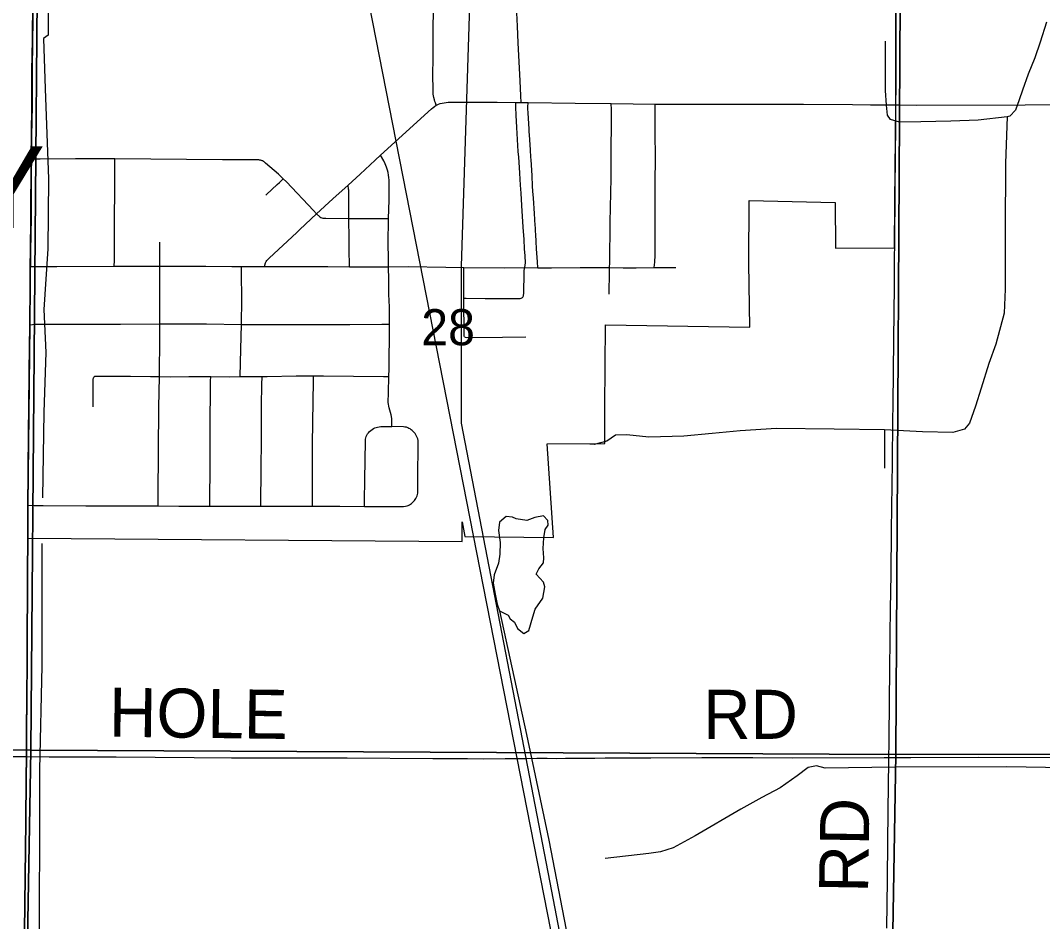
# Model space of a CAD drawing. Extents: x 0 to 34, y 0 to 22.
# Drawn here: x 3.136 to 4.321, y 19.331 to 20.375 of the extents above; entities that cross this region are included whole.
import ezdxf

# ---------------------------------------------------------------- set-up
doc = ezdxf.new("R2010")
doc.units = 0
for name, color, linetype in [('Default', 7, 'Continuous'), ('GM_X_City_Street', 7, 'Continuous'), ('GM_X_Corporation_Text', 7, 'Continuous'), ('GM_X_County_Road', 7, 'Continuous'), ('GM_X_Minor_Lake', 7, 'Continuous'), ('GM_X_Minor_River', 7, 'Continuous'), ('GM_X_Rail_Line', 7, 'Continuous'), ('GM_X_Section', 7, 'Continuous'), ('GM_X_Section_Text', 7, 'Continuous'), ('GM_X_State_Route', 7, 'Continuous'), ('GM_X_Township_Road', 7, 'Continuous'), ('GM_X_Township_Road_Text', 7, 'Continuous')]:
    doc.layers.add(name, color=color, linetype=linetype)

msp = doc.modelspace()

# ---------------------------------------------------------------- linework, layer by layer
at = {"layer": 'Default'}
for points in [[(3.1509, 20.3978), (3.1497, 20.2765), (3.1489, 20.2151), (3.1486, 20.1465), (3.1478, 20.0903), (3.1472, 20.0228), (3.1452, 19.8136), (3.1449, 19.775), (3.6483, 19.7709), (3.6482, 19.7779), (3.6483, 19.7938), (3.6515, 19.7769), (3.7543, 19.7756), (3.747, 19.8843), (3.8135, 19.8846), (3.8135, 19.9261), (3.8144, 20.022), (3.9815, 20.0192), (3.9805, 20.0931), (3.9808, 20.1661), (4.0804, 20.1638), (4.081, 20.1108), (4.1492, 20.1113), (4.1497, 20.1638), (4.1507, 20.2775), (4.1512, 20.5281)], [(3.1509, 20.3978), (3.1503, 20.3518), (3.1498, 20.3169), (3.1497, 20.2765), (3.1493, 20.2417), (3.1489, 20.2181), (3.1489, 20.2151), (3.1489, 20.1988), (3.1486, 20.1602), (3.1486, 20.1465), (3.148, 20.108), (3.1478, 20.0903), (3.1478, 20.0669), (3.1472, 20.0228), (3.1469, 19.9948), (3.1468, 19.9686), (3.1461, 19.9245), (3.1459, 19.8999), (3.1455, 19.8495), (3.1452, 19.8136), (3.145, 19.7885), (3.1449, 19.775), (3.1445, 19.7344), (3.1448, 19.7114), (3.1445, 19.6964), (3.1443, 19.6784), (3.1444, 19.656), (3.1443, 19.6349), (3.1442, 19.6188), (3.144, 19.6032), (3.144, 19.5871), (3.1437, 19.5542), (3.1436, 19.5246), (3.1436, 19.5224), (3.1433, 19.4963), (3.1426, 19.4466), (3.1411, 19.3192)], [(3.1411, 19.3192), (3.1426, 19.4466), (3.1433, 19.4963), (3.1436, 19.5224), (3.1436, 19.5246), (3.1437, 19.5542), (3.144, 19.5871), (3.144, 19.6032), (3.1442, 19.6188), (3.1443, 19.6349), (3.1444, 19.656), (3.1443, 19.6784), (3.1445, 19.6964), (3.1448, 19.7114), (3.1445, 19.7344), (3.1449, 19.775), (3.145, 19.7885), (3.1452, 19.8136), (3.1455, 19.8495), (3.1459, 19.8999), (3.1461, 19.9245), (3.1468, 19.9686), (3.1469, 19.9948), (3.1472, 20.0228), (3.1478, 20.0669), (3.1478, 20.0903), (3.148, 20.108), (3.1486, 20.1465), (3.1486, 20.1602), (3.1489, 20.1988), (3.1489, 20.2151), (3.1489, 20.2181), (3.1493, 20.2417), (3.1497, 20.2765), (3.1498, 20.3169), (3.1503, 20.3518), (3.1509, 20.3978)]]:
    msp.add_lwpolyline(points, dxfattribs=at)
at = {"layer": 'GM_X_City_Street'}
for points in [[(3.6183, 20.2765), (3.6173, 20.2792), (3.6167, 20.2808), (3.6161, 20.2829), (3.6154, 20.2854), (3.6149, 20.2892), (3.6148, 20.293), (3.6145, 20.3135), (3.6147, 20.3294), (3.6149, 20.3686), (3.6166, 20.4417), (3.6174, 20.4802), (3.6179, 20.5203), (3.618, 20.5322)], [(3.7168, 20.2798), (3.7164, 20.2875), (3.7156, 20.3048), (3.7134, 20.3488), (3.7125, 20.368), (3.7108, 20.3996), (3.7102, 20.4101), (3.7092, 20.4275), (3.7088, 20.4343), (3.7083, 20.4442), (3.7067, 20.4746), (3.7063, 20.4832), (3.705, 20.5055), (3.7045, 20.5214), (3.7041, 20.5319)], [(3.7211, 20.0885), (3.7217, 20.094), (3.7212, 20.1022), (3.7207, 20.1101), (3.7201, 20.1208), (3.7191, 20.1351), (3.7187, 20.1419), (3.7179, 20.1537), (3.7175, 20.1605), (3.7166, 20.1748), (3.716, 20.184), (3.7152, 20.1977), (3.7144, 20.2107), (3.7139, 20.2162), (3.7134, 20.2228), (3.7117, 20.2508), (3.7109, 20.2651), (3.7107, 20.2742), (3.7107, 20.2798)], [(3.7359, 20.0883), (3.7355, 20.095), (3.7346, 20.1102), (3.734, 20.1188), (3.7336, 20.1268), (3.7334, 20.1305), (3.7333, 20.1324), (3.7332, 20.1348), (3.7331, 20.1373), (3.7322, 20.1509), (3.731, 20.1688), (3.7304, 20.1768), (3.73, 20.1829), (3.7293, 20.1952), (3.7282, 20.2132), (3.728, 20.2162), (3.7274, 20.2248), (3.7263, 20.2421), (3.7261, 20.2457), (3.7259, 20.248), (3.7259, 20.2491), (3.7248, 20.2674), (3.7246, 20.2726), (3.7246, 20.2744), (3.7247, 20.2798)], [(3.8185, 20.0578), (3.8188, 20.0667), (3.819, 20.0747), (3.8192, 20.0884), (3.8195, 20.0939), (3.82, 20.1411), (3.8209, 20.1919), (3.821, 20.2251), (3.8213, 20.255), (3.8212, 20.2717), (3.8211, 20.2784)], [(3.871, 20.0884), (3.8714, 20.0947), (3.8718, 20.1029), (3.872, 20.1349), (3.8718, 20.1807), (3.8722, 20.2214), (3.8721, 20.2392), (3.872, 20.2693), (3.872, 20.2779)], [(3.5667, 19.9043), (3.5667, 19.9133), (3.5664, 19.9158), (3.566, 19.9179), (3.5638, 19.9259), (3.5633, 19.9279), (3.563, 19.9301), (3.5627, 19.9319), (3.563, 19.9436), (3.5635, 19.9622), (3.5637, 19.971), (3.5643, 20.0194), (3.5642, 20.0227), (3.5641, 20.0341), (3.564, 20.0426), (3.5637, 20.0504), (3.5635, 20.0571), (3.5632, 20.0743), (3.5631, 20.0894), (3.5631, 20.0965), (3.5627, 20.1188), (3.5628, 20.1427), (3.5629, 20.1452), (3.5632, 20.1558), (3.5637, 20.167), (3.5638, 20.1812), (3.5638, 20.1897), (3.5635, 20.1927), (3.5631, 20.1956), (3.5625, 20.1986), (3.5619, 20.2013), (3.5608, 20.2047), (3.5593, 20.2085), (3.5575, 20.2122), (3.5537, 20.2188)], [(3.1492, 20.2146), (3.1593, 20.2146), (3.2003, 20.2147), (3.246, 20.2149), (3.3705, 20.2137), (3.4123, 20.2135), (3.4131, 20.2134), (3.4141, 20.2132), (3.4149, 20.213), (3.416, 20.2126)], [(3.2452, 20.09), (3.2453, 20.0968), (3.2456, 20.1353), (3.2459, 20.1883), (3.246, 20.2149)], [(3.4795, 20.1507), (3.4761, 20.1545), (3.4446, 20.1877), (3.441, 20.1911), (3.4354, 20.1965), (3.4204, 20.2096), (3.419, 20.2108), (3.418, 20.2115), (3.417, 20.2121), (3.416, 20.2126)], [(3.4209, 20.1723), (3.4218, 20.1732), (3.434, 20.1847), (3.4366, 20.1871), (3.441, 20.1911)], [(3.5172, 20.1454), (3.5171, 20.1627), (3.517, 20.176), (3.5169, 20.178), (3.5167, 20.1793), (3.5161, 20.1838)], [(3.4795, 20.1507), (3.4834, 20.1472), (3.4844, 20.1466), (3.4856, 20.1461), (3.4868, 20.1458), (3.4883, 20.1457), (3.4903, 20.1456), (3.5172, 20.1454), (3.52, 20.1454), (3.5559, 20.1452), (3.5629, 20.1452)], [(3.5177, 20.0894), (3.5175, 20.1101), (3.5173, 20.1286), (3.5172, 20.1381), (3.5172, 20.1454)], [(3.2962, 19.8124), (3.2962, 19.8245), (3.2969, 19.9263), (3.2975, 19.9622), (3.2981, 20.0085), (3.2981, 20.0231), (3.2982, 20.0329), (3.298, 20.0712), (3.2979, 20.09), (3.2981, 20.1178)], [(3.3912, 19.9621), (3.3919, 19.9939), (3.3927, 20.0226), (3.3929, 20.0519), (3.3928, 20.0821), (3.3928, 20.0897)], [(3.4194, 20.0897), (3.4584, 20.0896), (3.4926, 20.0895), (3.5177, 20.0894), (3.5298, 20.0894), (3.549, 20.0894), (3.5631, 20.0894), (3.5857, 20.0895), (3.6295, 20.089), (3.6503, 20.0887), (3.6977, 20.0882), (3.7211, 20.0885), (3.7359, 20.0883), (3.7517, 20.0883), (3.7852, 20.0884), (3.8192, 20.0884), (3.8349, 20.0881), (3.8498, 20.0881), (3.871, 20.0884), (3.8807, 20.0885), (3.8961, 20.0887)], [(3.6512, 20.0083), (3.6505, 20.0093), (3.6503, 20.0528), (3.6503, 20.0812), (3.6503, 20.0887)], [(3.6503, 20.0528), (3.653, 20.0528), (3.675, 20.0527), (3.7157, 20.0526), (3.7167, 20.0529), (3.7174, 20.0533), (3.7181, 20.0537), (3.7186, 20.0541), (3.7191, 20.0549), (3.7194, 20.0557), (3.7196, 20.0566), (3.7198, 20.0584), (3.72, 20.0827), (3.7202, 20.085), (3.7211, 20.0885)], [(3.1474, 20.0222), (3.1535, 20.0228), (3.2031, 20.0229), (3.2523, 20.023), (3.2981, 20.0231), (3.3522, 20.0232), (3.3927, 20.0226), (3.4118, 20.0223), (3.5181, 20.0225), (3.5553, 20.0227), (3.5642, 20.0227)], [(3.6512, 20.0083), (3.652, 20.0077), (3.653, 20.0075), (3.6952, 20.0079), (3.722, 20.0082)], [(3.2207, 19.9269), (3.2206, 19.9588), (3.2208, 19.9596), (3.2211, 19.9603), (3.2216, 19.9614)], [(3.2216, 19.9614), (3.2221, 19.9619), (3.2227, 19.9624), (3.2233, 19.9625), (3.224, 19.9626), (3.2639, 19.9624), (3.2872, 19.9623), (3.2975, 19.9622), (3.3104, 19.9619), (3.3316, 19.9622), (3.3571, 19.9621), (3.3788, 19.962), (3.3912, 19.9621), (3.4037, 19.9621), (3.4164, 19.9622), (3.4222, 19.9622), (3.456, 19.9628), (3.4761, 19.963), (3.4878, 19.9631), (3.5572, 19.9623), (3.5635, 19.9622)], [(3.3558, 19.812), (3.3558, 19.8169), (3.3563, 19.8591), (3.3564, 19.8994), (3.3569, 19.9568), (3.3571, 19.9621)], [(3.4152, 19.8121), (3.4152, 19.8189), (3.4154, 19.8502), (3.4158, 19.8933), (3.4158, 19.9284), (3.4162, 19.9524), (3.4164, 19.9622)], [(3.4748, 19.812), (3.4748, 19.819), (3.4751, 19.8466), (3.4751, 19.8836), (3.4758, 19.9338), (3.476, 19.9565), (3.4761, 19.963)], [(3.5352, 19.8117), (3.5352, 19.8186), (3.5354, 19.8424), (3.5362, 19.8878), (3.5363, 19.8897), (3.5366, 19.8911), (3.537, 19.8926), (3.5377, 19.8942), (3.5387, 19.8957), (3.5397, 19.897), (3.5411, 19.8985), (3.5424, 19.8997), (3.5439, 19.9009), (3.5455, 19.9018), (3.5471, 19.9026), (3.5486, 19.9031), (3.5504, 19.9036), (3.552, 19.904), (3.554, 19.9042), (3.5667, 19.9043)], [(3.5909, 19.8161), (3.592, 19.8172), (3.5931, 19.8184), (3.594, 19.8196), (3.5947, 19.8208), (3.5955, 19.8222), (3.5961, 19.8238), (3.5965, 19.8253), (3.5969, 19.8271), (3.5971, 19.8289), (3.5968, 19.8426), (3.5975, 19.8865), (3.5974, 19.8882), (3.597, 19.8898), (3.5963, 19.8915), (3.5955, 19.8931), (3.5948, 19.8945), (3.5938, 19.8961), (3.5929, 19.8974), (3.5917, 19.8986), (3.5905, 19.8997), (3.5894, 19.9005), (3.5881, 19.9014), (3.5867, 19.9021), (3.5853, 19.9028), (3.5837, 19.9033), (3.582, 19.9036), (3.5803, 19.9037), (3.5667, 19.9043)], [(3.1454, 19.813), (3.1523, 19.8128), (3.1628, 19.8126), (3.2124, 19.8124), (3.2373, 19.8123), (3.2845, 19.8124), (3.2962, 19.8124), (3.3199, 19.8121), (3.3535, 19.812), (3.3558, 19.812), (3.3795, 19.812), (3.4053, 19.8121), (3.4152, 19.8121), (3.4507, 19.8119), (3.4748, 19.812), (3.5064, 19.812), (3.5352, 19.8117), (3.5598, 19.8114), (3.5805, 19.8116), (3.5827, 19.8118), (3.5845, 19.8123), (3.5859, 19.8127), (3.5872, 19.8134), (3.5885, 19.8142), (3.5897, 19.815), (3.5909, 19.8161)]]:
    msp.add_lwpolyline(points, dxfattribs=at)
at = {"layer": 'GM_X_County_Road'}
for points in [[(3.1492, 20.2146), (3.1492, 20.2175), (3.1495, 20.2411), (3.1499, 20.276), (3.15, 20.3164), (3.1505, 20.3512), (3.1511, 20.3972), (3.1517, 20.4538), (3.1519, 20.4887), (3.1523, 20.5141), (3.1528, 20.5377)], [(3.1481, 20.0898), (3.1482, 20.1074), (3.1489, 20.146), (3.1488, 20.1597), (3.1491, 20.1982), (3.1492, 20.2146)], [(3.1474, 20.0222), (3.148, 20.0664), (3.1481, 20.0898)], [(3.1454, 19.813), (3.1457, 19.8489), (3.1461, 19.8993), (3.1463, 19.924), (3.147, 19.9681), (3.1472, 19.9942), (3.1474, 20.0222)], [(3.1452, 19.7754), (3.1452, 19.788), (3.1454, 19.813)], [(3.1438, 19.5218), (3.1438, 19.524), (3.144, 19.5536), (3.1443, 19.5865), (3.1443, 19.6027), (3.1444, 19.6182), (3.1445, 19.6344), (3.1446, 19.6555), (3.1445, 19.6779), (3.1447, 19.6959), (3.145, 19.7108), (3.1448, 19.7338), (3.1452, 19.7744), (3.1452, 19.7754)], [(3.1414, 19.3187), (3.1428, 19.446), (3.1435, 19.4957), (3.1438, 19.5218)]]:
    msp.add_lwpolyline(points, dxfattribs=at)
at = {"layer": 'GM_X_Minor_Lake'}
msp.add_line((3.7234, 19.7954), (3.7109, 19.7972), dxfattribs=at)
msp.add_lwpolyline([(3.7109, 19.7972), (3.7068, 19.7992), (3.6992, 19.8001), (3.6915, 19.7935), (3.6905, 19.7836), (3.6924, 19.7699), (3.6921, 19.7563), (3.6903, 19.7457), (3.6854, 19.7325), (3.6844, 19.7227), (3.6864, 19.7101), (3.6888, 19.6983), (3.6916, 19.6906), (3.7017, 19.6855), (3.7039, 19.6812), (3.7091, 19.6777), (3.7123, 19.67), (3.7197, 19.6642), (3.7255, 19.6678), (3.7301, 19.6836), (3.7329, 19.6927), (3.742, 19.7054), (3.7442, 19.7186), (3.7424, 19.7239), (3.7339, 19.7333), (3.7371, 19.7392), (3.7426, 19.7463), (3.7431, 19.752), (3.7422, 19.7627), (3.7429, 19.7752), (3.7447, 19.785), (3.7478, 19.7898), (3.7476, 19.7955), (3.7424, 19.8006), (3.7325, 19.7989), (3.7234, 19.7954)], dxfattribs=at)
at = {"layer": 'GM_X_Minor_River'}
for points in [[(3.1715, 20.9), (3.1702, 20.8216), (3.1694, 20.729), (3.1695, 20.611), (3.1686, 20.5131), (3.1685, 20.3579), (3.1631, 20.3539), (3.1651, 20.2954), (3.1689, 20.1913), (3.1684, 20.1101), (3.1636, 20.04), (3.1658, 19.9899), (3.1637, 19.9209), (3.162, 19.8215)], [(4.3254, 20.3728), (4.3181, 20.3498), (4.3119, 20.3314), (4.3041, 20.3125), (4.2978, 20.294), (4.2937, 20.2829), (4.2897, 20.271), (4.283, 20.2638), (4.2799, 20.2631), (4.2463, 20.2594), (4.2147, 20.2582), (4.1798, 20.2572), (4.1552, 20.257), (4.1446, 20.2601), (4.141, 20.2649), (4.1401, 20.2767), (4.139, 20.2935), (4.1389, 20.3508)], [(4.2799, 20.2631), (4.2778, 20.2096), (4.2774, 20.1311), (4.2776, 20.0635), (4.2762, 20.0355), (4.2666, 19.9997), (4.2586, 19.9774), (4.2498, 19.9488), (4.2432, 19.9278), (4.2363, 19.9082), (4.2304, 19.9011), (4.2167, 19.8973), (4.1819, 19.8981), (4.1376, 19.9003), (4.0793, 19.901), (4.0127, 19.9018), (3.9706, 19.8994), (3.9379, 19.8961), (3.9053, 19.893), (3.8645, 19.8919), (3.8391, 19.8946), (3.8262, 19.8942), (3.8158, 19.8872), (3.8013, 19.8834), (3.7964, 19.8839)], [(4.1376, 19.9003), (4.1376, 19.8559)], [(3.1562, 19.2065), (3.1585, 19.2698), (3.1591, 19.5062), (3.1617, 19.6268), (3.1618, 19.7687)], [(3.6916, 19.6906), (3.7229, 19.5472), (3.7486, 19.4248), (3.7755, 19.2871), (3.8021, 19.1552)], [(4.7979, 19.5125), (4.7112, 19.5115), (4.6024, 19.5107), (4.5135, 19.5106), (4.3911, 19.5079), (4.2794, 19.5098), (4.1499, 19.5095), (4.0688, 19.5085), (4.059, 19.511), (4.0491, 19.5089), (4.0364, 19.4994), (4.0167, 19.4854), (3.9956, 19.4742), (3.9711, 19.4607), (3.9184, 19.4298), (3.8927, 19.416), (3.8782, 19.4114), (3.8645, 19.4094), (3.814, 19.4035)]]:
    msp.add_lwpolyline(points, dxfattribs=at)
at = {"layer": 'GM_X_Rail_Line'}
for points in [[(3.4414, 20.9), (3.5016, 20.5918), (3.7507, 19.321), (3.8733, 18.7042), (3.9207, 18.4339), (3.9385, 18.3568), (3.9629, 18.2975), (3.9974, 18.239), (4.1223, 18.078), (4.3281, 17.8226), (4.3689, 17.7633), (4.4066, 17.7097), (4.4454, 17.6387), (4.4793, 17.5709), (4.5132, 17.4611), (4.5342, 17.361), (4.5504, 17.2625), (4.562, 17.1188)], [(3.6732, 20.9), (3.6471, 20.09), (3.6471, 19.9081), (3.752, 19.3659), (3.9326, 18.4227), (3.949, 18.3555), (3.9754, 18.3001), (4.0116, 18.2329), (4.0712, 18.1586), (4.3307, 17.8397), (4.4282, 17.7343), (4.663, 17.5576), (4.8455, 17.4299), (4.9093, 17.3662)]]:
    msp.add_lwpolyline(points, dxfattribs=at)
at = {"layer": 'GM_X_Section'}
for points in [[(3.1572, 20.5385), (3.1487, 19.529), (2.1432, 19.5299), (2.1468, 20.5444)], [(4.1565, 20.5312), (4.1507, 19.5243), (3.1487, 19.529), (3.1572, 20.5385)], [(5.1605, 20.536), (5.1538, 19.525), (4.1507, 19.5243), (4.1565, 20.5312)], [(2.1432, 19.5299), (3.1487, 19.529), (3.1307, 18.5181), (3.1239, 18.5181), (2.1356, 18.5238), (2.1418, 18.8909)], [(4.1507, 19.5243), (4.1339, 18.5191), (4.1085, 18.519), (3.1307, 18.5181), (3.1487, 19.529)], [(5.1538, 19.525), (5.1313, 18.516), (5.1123, 18.5161), (4.1339, 18.5191), (4.1507, 19.5243)]]:
    msp.add_lwpolyline(points, close=True, dxfattribs=at)
at = {"layer": 'GM_X_State_Route'}
for p, q in [((4.1007, 20.2773), (4.1216, 20.2772)), ((4.1216, 20.2772), (4.151, 20.277))]:
    msp.add_line(p, q, dxfattribs=at)
for points in [[(3.1528, 20.5377), (3.1523, 20.5141), (3.1519, 20.4887), (3.1517, 20.4538), (3.1511, 20.3972), (3.1505, 20.3512), (3.15, 20.3164), (3.1499, 20.276), (3.1495, 20.2411), (3.1492, 20.2175), (3.1492, 20.2146)], [(3.4604, 20.1327), (3.4795, 20.1507), (3.4985, 20.168), (3.5161, 20.1838), (3.5301, 20.1968), (3.5474, 20.2128), (3.5537, 20.2188), (3.6129, 20.2725), (3.6148, 20.2741), (3.6162, 20.2752), (3.6183, 20.2765), (3.6194, 20.2771), (3.621, 20.2778), (3.623, 20.2785), (3.625, 20.279), (3.6274, 20.2795), (3.6298, 20.2799), (3.632, 20.2801), (3.6345, 20.2802), (3.689, 20.2801), (3.7107, 20.2798), (3.7168, 20.2798), (3.7247, 20.2798), (3.7792, 20.2788), (3.8211, 20.2784), (3.872, 20.2779), (3.9331, 20.2777), (4.0437, 20.2776), (4.1007, 20.2773)], [(4.151, 20.277), (4.1544, 20.2769), (4.1743, 20.2767), (4.3008, 20.2769), (4.3849, 20.2779), (4.4284, 20.2784), (4.4645, 20.2784), (4.5303, 20.279), (4.5626, 20.2794), (4.6054, 20.2791), (4.6421, 20.2792), (4.6629, 20.2793), (4.7213, 20.2795), (4.7716, 20.2796), (4.8276, 20.2797), (4.8723, 20.2799), (4.9892, 20.2798), (5.1594, 20.2793)], [(3.1492, 20.2146), (3.1491, 20.1982), (3.1488, 20.1597), (3.1489, 20.146), (3.1482, 20.1074), (3.1481, 20.0898)], [(3.4248, 20.0994), (3.4568, 20.1292), (3.4604, 20.1327)], [(3.3815, 20.0897), (3.3928, 20.0897), (3.4026, 20.0896), (3.4194, 20.0897), (3.4206, 20.0939), (3.4213, 20.0955), (3.4219, 20.0965), (3.4226, 20.0974), (3.4248, 20.0994)], [(3.1481, 20.0898), (3.1786, 20.0897), (3.2452, 20.09), (3.247, 20.09), (3.2623, 20.09)], [(3.2623, 20.09), (3.2979, 20.09), (3.3515, 20.0899), (3.3815, 20.0897)]]:
    msp.add_lwpolyline(points, dxfattribs=at)
at = {"layer": 'GM_X_Township_Road'}
for points in [[(4.151, 20.277), (4.1513, 20.2992), (4.1512, 20.3203), (4.1511, 20.3495), (4.1514, 20.478), (4.1519, 20.5279)], [(4.1495, 20.1107), (4.15, 20.1833), (4.1503, 20.2131), (4.1506, 20.2272), (4.1507, 20.2439), (4.1508, 20.2625), (4.151, 20.277)], [(4.1493, 20.0948), (4.1494, 20.1042), (4.1495, 20.1107)], [(4.1428, 19.5207), (4.1431, 19.5377), (4.1436, 19.5905), (4.1437, 19.6179), (4.1444, 19.6627), (4.1447, 19.6931), (4.1453, 19.7329), (4.1459, 19.7842), (4.147, 19.863), (4.1473, 19.9107), (4.1477, 19.93), (4.1484, 20.0052), (4.1492, 20.0674), (4.1493, 20.0885), (4.1493, 20.0948)], [(2.1452, 19.5337), (2.1567, 19.5336), (2.2033, 19.5331), (2.2593, 19.5323), (2.3276, 19.5314), (2.3991, 19.5306), (2.4519, 19.5299), (2.5079, 19.5293), (2.5234, 19.5292), (2.5763, 19.5285), (2.6073, 19.528), (2.6167, 19.5279), (2.654, 19.5275), (2.7472, 19.5264), (2.8, 19.5258), (2.8404, 19.5254), (2.8964, 19.5247), (2.9896, 19.5236), (3.0176, 19.5232), (3.0518, 19.5227), (3.117, 19.522), (3.1419, 19.5219), (3.1438, 19.5218)], [(3.1438, 19.5218), (3.1699, 19.5216), (3.1978, 19.5214), (3.2476, 19.5214), (3.3377, 19.5208), (3.3812, 19.5204), (3.403, 19.5203), (3.4713, 19.5204), (3.5149, 19.5203), (3.6143, 19.5196), (3.6485, 19.5194), (3.6547, 19.5194), (3.6732, 19.5192), (3.6982, 19.5196), (3.7181, 19.5197)], [(3.7181, 19.5197), (3.722, 19.5197), (3.7349, 19.52), (3.741, 19.5199), (3.747, 19.5198), (3.7574, 19.5197), (3.7679, 19.5199), (3.774, 19.5198), (3.7829, 19.5199), (3.7954, 19.52), (3.802, 19.5199), (3.814, 19.5202), (3.8668, 19.5202), (3.9259, 19.5205), (3.985, 19.5205), (4.0316, 19.5204), (4.1373, 19.5207), (4.1428, 19.5207)], [(4.1403, 19.323), (4.141, 19.3791), (4.1415, 19.4233), (4.1424, 19.4905), (4.1427, 19.5141), (4.1428, 19.5207)], [(4.1428, 19.5207), (4.1683, 19.5208), (4.2461, 19.5209), (4.3704, 19.5205), (4.4326, 19.5201), (4.5196, 19.5199), (4.675, 19.5208), (4.7216, 19.5212), (4.7434, 19.521), (4.759, 19.5207), (4.7745, 19.5201), (4.7807, 19.5198), (4.8024, 19.5192), (4.8179, 19.5189), (4.8676, 19.5186), (4.9111, 19.5187), (4.9795, 19.5192), (5.051, 19.5194), (5.0914, 19.5194), (5.1318, 19.5196), (5.15, 19.5196)]]:
    msp.add_lwpolyline(points, dxfattribs=at)

# ---------------------------------------------------------------- texts
at = {"layer": 'GM_X_Corporation_Text'}
msp.add_text('LUCKEY', height=0.0947, rotation=0, dxfattribs=at).set_placement((2.6584, 20.1342))
at = {"layer": 'GM_X_Section_Text'}
msp.add_text('28', height=0.04186, rotation=0, dxfattribs=at).set_placement((3.6009, 19.9984))
at = {"layer": 'GM_X_Township_Road_Text'}
for s, rotation, p in [('HOLE', 359.2621, (3.2389, 19.5448)), ('RD', 0, (3.9276, 19.5423)), ('RD', 89.0287, (4.1186, 19.3636))]:
    msp.add_text(s, height=0.05682, rotation=rotation, dxfattribs=at).set_placement(p)

doc.saveas('drawing.dxf')
